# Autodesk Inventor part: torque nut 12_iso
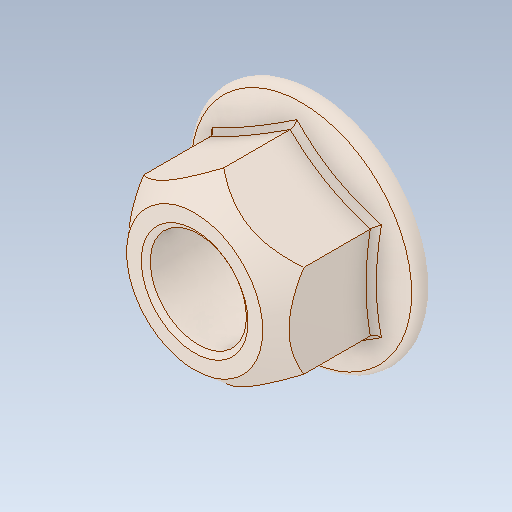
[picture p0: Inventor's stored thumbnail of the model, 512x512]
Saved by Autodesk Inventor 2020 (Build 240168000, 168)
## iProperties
Created: 1999-08
Part Number: torque nut 12_iso
Material: Ogólny
Document SubType Name: Modeling
Designer: Tomasz
Density: 1 g/cm^3
Appearance: Domyślna
Sending System: SolidWorks 2017
Last Author: Tomasz
Last Saved: 2017-11-19
Author: Tomasz
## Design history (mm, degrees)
feature "EndChamfer"
node "Bryła1"
